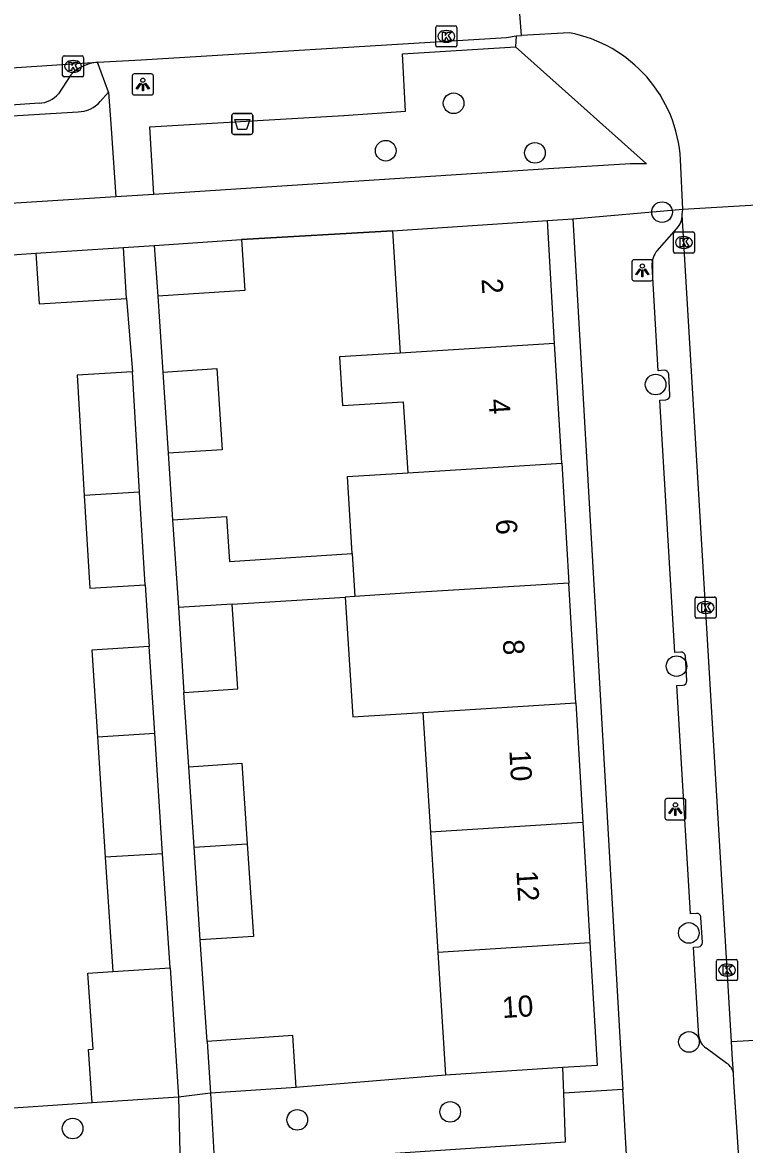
# Model space of a CAD drawing. Extents: x 159053 to 160041, y 380450 to 381422.
# Drawn here: x 159582.9 to 159617.1, y 381129.1 to 381182.3 of the extents above; entities that cross this region are included whole.
import ezdxf

# ---------------------------------------------------------------- set-up
doc = ezdxf.new("R2010")
doc.units = 0
for name, color, linetype in [('IMGEO_Afvalbak', 7, 'Continuous'), ('IMGEO_Boom', 7, 'Continuous'), ('IMGEO_Groenvoorziening', 7, 'Continuous'), ('IMGEO_Kolk', 7, 'Continuous'), ('IMGEO_Lichtpunt', 7, 'Continuous'), ('IMGEO_Muur', 7, 'Continuous'), ('IMGEO_Pand', 7, 'Continuous'), ('IMGEO_Pand_nummerreeks', 7, 'Continuous'), ('IMGEO_Rijbaan_lokaal_open', 7, 'Continuous'), ('IMGEO_Voetpad_open', 7, 'Continuous')]:
    doc.layers.add(name, color=color, linetype=linetype)

msp = doc.modelspace()

# ---------------------------------------------------------------- linework, layer by layer
at = {"layer": 'IMGEO_Afvalbak'}
for p, q in [((159592.854, 381177.078), (159592.854, 381177.878)), ((159592.854, 381177.878), (159592.854, 381177.078)), ((159592.954, 381177.978), (159593.744, 381177.978)), ((159593.744, 381177.978), (159592.954, 381177.978)), ((159593.844, 381177.878), (159593.844, 381177.078)), ((159593.844, 381177.078), (159593.844, 381177.878)), ((159593.744, 381176.978), (159592.954, 381176.978)), ((159592.954, 381176.978), (159593.744, 381176.978))]:
    msp.add_line(p, q, dxfattribs=at)
msp.add_lwpolyline([(159592.997, 381177.692), (159593.701, 381177.692), (159593.552, 381177.222), (159593.146, 381177.222), (159592.997, 381177.692)], dxfattribs=at)
for centre, start, end in [((159592.954, 381177.878), 90, 180), ((159592.954, 381177.878), 90, 180), ((159593.744, 381177.878), 0, 90), ((159593.744, 381177.878), 360, 90), ((159592.954, 381177.078), 180, 270), ((159592.954, 381177.078), 180, 270), ((159593.744, 381177.078), 270, 0), ((159593.744, 381177.078), 270, 0)]:
    msp.add_arc(centre, 0.1, start, end, dxfattribs=at)
at = {"layer": 'IMGEO_Boom'}
for centre in [(159603.362, 381178.456), (159600.148, 381176.211), (159607.215, 381176.108), (159613.236, 381173.3), (159612.932, 381165.134), (159613.922, 381151.794), (159614.502, 381139.152), (159614.511, 381133.992), (159603.2, 381130.677), (159595.954, 381130.298), (159585.316, 381129.889)]:
    msp.add_circle(centre, 0.489, dxfattribs=at)
at = {"layer": 'IMGEO_Groenvoorziening'}
for points in [[(159608.578, 381131.566), (159608.535, 381132.773)], [(159602.981, 381132.424), (159596.059, 381131.851), (159595.908, 381131.838)], [(159586.241, 381131.103), (159581.089, 381130.759)]]:
    msp.add_lwpolyline(points, dxfattribs=at)
at = {"layer": 'IMGEO_Kolk'}
for p, q in [((159602.516, 381181.199), (159602.516, 381182.051)), ((159602.591, 381182.125), (159603.443, 381182.125)), ((159603.517, 381182.051), (159603.517, 381181.199)), ((159603.004, 381181.905), (159603.029, 381181.905)), ((159603.443, 381181.125), (159602.591, 381181.125)), ((159603.027, 381181.345), (159603.002, 381181.345)), ((159584.836, 381179.778), (159584.836, 381180.63)), ((159584.911, 381180.704), (159585.763, 381180.704)), ((159585.324, 381180.484), (159585.349, 381180.484)), ((159585.837, 381180.63), (159585.837, 381179.778)), ((159585.347, 381179.924), (159585.322, 381179.924)), ((159585.763, 381179.704), (159584.911, 381179.704)), ((159613.77, 381171.438), (159613.77, 381172.29)), ((159613.845, 381172.364), (159614.697, 381172.364)), ((159614.258, 381172.144), (159614.283, 381172.144)), ((159614.771, 381172.29), (159614.771, 381171.438)), ((159614.281, 381171.584), (159614.256, 381171.584)), ((159614.697, 381171.364), (159613.845, 381171.364)), ((159614.796, 381154.142), (159614.796, 381154.994)), ((159614.871, 381155.068), (159615.723, 381155.068)), ((159615.797, 381154.994), (159615.797, 381154.142)), ((159615.284, 381154.848), (159615.309, 381154.848)), ((159615.723, 381154.068), (159614.871, 381154.068)), ((159615.307, 381154.288), (159615.282, 381154.288)), ((159615.889, 381137.897), (159616.741, 381137.897)), ((159615.814, 381136.971), (159615.814, 381137.823)), ((159616.302, 381137.677), (159616.327, 381137.677)), ((159616.815, 381137.823), (159616.815, 381136.971)), ((159616.741, 381136.897), (159615.889, 381136.897)), ((159616.325, 381137.117), (159616.3, 381137.117))]:
    msp.add_line(p, q, dxfattribs=at)
for points in [[(159602.516, 381181.199), (159602.516, 381182.051)], [(159602.591, 381182.125), (159603.443, 381182.125)], [(159603.517, 381182.051), (159603.517, 381181.199)], [(159602.837, 381181.825), (159602.96, 381181.825), (159602.96, 381181.674), (159603.09, 381181.825), (159603.254, 381181.825), (159603.108, 381181.674), (159603.261, 381181.425), (159603.109, 381181.425), (159603.024, 381181.589), (159602.96, 381181.522), (159602.96, 381181.425), (159602.837, 381181.425), (159602.837, 381181.825)], [(159603.443, 381181.125), (159602.591, 381181.125)], [(159584.836, 381179.778), (159584.836, 381180.63)], [(159584.911, 381180.704), (159585.763, 381180.704)], [(159585.837, 381180.63), (159585.837, 381179.778)], [(159585.157, 381180.404), (159585.28, 381180.404), (159585.28, 381180.253), (159585.41, 381180.404), (159585.574, 381180.404), (159585.428, 381180.253), (159585.581, 381180.004), (159585.429, 381180.004), (159585.344, 381180.168), (159585.28, 381180.101), (159585.28, 381180.004), (159585.157, 381180.004), (159585.157, 381180.404)], [(159585.763, 381179.704), (159584.911, 381179.704)], [(159613.77, 381171.438), (159613.77, 381172.29)], [(159613.845, 381172.364), (159614.697, 381172.364)], [(159614.091, 381172.064), (159614.214, 381172.064), (159614.214, 381171.913), (159614.344, 381172.064), (159614.508, 381172.064), (159614.362, 381171.913), (159614.515, 381171.664), (159614.363, 381171.664), (159614.278, 381171.828), (159614.214, 381171.761), (159614.214, 381171.664), (159614.091, 381171.664), (159614.091, 381172.064)], [(159614.771, 381172.29), (159614.771, 381171.438)], [(159614.697, 381171.364), (159613.845, 381171.364)], [(159614.796, 381154.142), (159614.796, 381154.994)], [(159614.871, 381155.068), (159615.723, 381155.068)], [(159615.797, 381154.994), (159615.797, 381154.142)], [(159615.117, 381154.768), (159615.24, 381154.768), (159615.24, 381154.617), (159615.37, 381154.768), (159615.534, 381154.768), (159615.388, 381154.617), (159615.541, 381154.368), (159615.389, 381154.368), (159615.304, 381154.532), (159615.24, 381154.465), (159615.24, 381154.368), (159615.117, 381154.368), (159615.117, 381154.768)], [(159615.723, 381154.068), (159614.871, 381154.068)], [(159615.889, 381137.897), (159616.741, 381137.897)], [(159615.814, 381136.971), (159615.814, 381137.823)], [(159616.135, 381137.597), (159616.258, 381137.597), (159616.258, 381137.446), (159616.388, 381137.597), (159616.552, 381137.597), (159616.406, 381137.446), (159616.559, 381137.197), (159616.407, 381137.197), (159616.322, 381137.361), (159616.258, 381137.294), (159616.258, 381137.197), (159616.135, 381137.197), (159616.135, 381137.597)], [(159616.815, 381137.823), (159616.815, 381136.971)], [(159616.741, 381136.897), (159615.889, 381136.897)]]:
    msp.add_lwpolyline(points, dxfattribs=at)
for centre, start, end in [((159602.593, 381182.049), 91.552, 178.448), ((159602.593, 381182.049), 91.552, 178.448), ((159603.441, 381182.049), 1.552, 88.448), ((159603.441, 381182.049), 1.552, 88.448), ((159602.593, 381181.201), 181.552, 268.448), ((159602.593, 381181.201), 181.552, 268.448), ((159603.441, 381181.201), 271.552, 358.448), ((159603.441, 381181.201), 271.552, 358.448), ((159584.913, 381180.628), 91.552, 178.448), ((159584.913, 381180.628), 91.552, 178.448), ((159585.761, 381180.628), 1.552, 88.448), ((159585.761, 381180.628), 1.552, 88.448), ((159584.913, 381179.78), 181.552, 268.448), ((159584.913, 381179.78), 181.552, 268.448), ((159585.761, 381179.78), 271.552, 358.448), ((159585.761, 381179.78), 271.552, 358.448), ((159613.847, 381172.288), 91.552, 178.448), ((159613.847, 381172.288), 91.552, 178.448), ((159614.695, 381172.288), 1.552, 88.448), ((159614.695, 381172.288), 1.552, 88.448), ((159613.847, 381171.44), 181.552, 268.448), ((159613.847, 381171.44), 181.552, 268.448), ((159614.695, 381171.44), 271.552, 358.448), ((159614.695, 381171.44), 271.552, 358.448), ((159614.873, 381154.992), 91.552, 178.448), ((159614.873, 381154.992), 91.552, 178.448), ((159615.721, 381154.992), 1.552, 88.448), ((159615.721, 381154.992), 1.552, 88.448), ((159614.873, 381154.144), 181.552, 268.448), ((159614.873, 381154.144), 181.552, 268.448), ((159615.721, 381154.144), 271.552, 358.448), ((159615.721, 381154.144), 271.552, 358.448), ((159615.891, 381137.821), 91.552, 178.448), ((159615.891, 381137.821), 91.552, 178.448), ((159616.739, 381137.821), 1.552, 88.448), ((159616.739, 381137.821), 1.552, 88.448), ((159615.891, 381136.973), 181.552, 268.448), ((159615.891, 381136.973), 181.552, 268.448), ((159616.739, 381136.973), 271.552, 358.448), ((159616.739, 381136.973), 271.552, 358.448)]:
    msp.add_arc(centre, 0.0765, start, end, dxfattribs=at)
for centre, major_axis, ratio, start_param, end_param in [((159603.003, 381181.625), (-0.387, 0.002), 0.722429, 4.712389, 7.853982), ((159603.028, 381181.625), (-0.39, 0.002), 0.717154, 1.570796, 4.712389), ((159585.323, 381180.204), (-0.387, 0.002), 0.722429, 4.712389, 7.853982), ((159585.348, 381180.204), (-0.39, 0.002), 0.717154, 1.570796, 4.712389), ((159614.257, 381171.864), (-0.387, 0.002), 0.722429, 4.712389, 7.853982), ((159614.282, 381171.864), (-0.39, 0.002), 0.717154, 1.570796, 4.712389), ((159615.283, 381154.568), (-0.387, 0.002), 0.722429, 4.712389, 7.853982), ((159615.308, 381154.568), (-0.39, 0.002), 0.717154, 1.570796, 4.712389), ((159616.301, 381137.397), (-0.387, 0.002), 0.722429, 4.712389, 7.853982), ((159616.326, 381137.397), (-0.39, 0.002), 0.717154, 1.570796, 4.712389)]:
    msp.add_ellipse(centre, major_axis=major_axis, ratio=ratio, start_param=start_param, end_param=end_param, dxfattribs=at)
at = {"layer": 'IMGEO_Lichtpunt'}
for p, q in [((159588.142, 381179.752), (159588.142, 381178.945)), ((159588.142, 381179.752), (159588.142, 381178.945)), ((159589.044, 381179.847), (159588.236, 381179.847)), ((159589.044, 381179.847), (159588.236, 381179.847)), ((159589.138, 381178.945), (159589.138, 381179.752)), ((159589.138, 381178.945), (159589.138, 381179.752)), ((159588.236, 381178.851), (159589.044, 381178.851)), ((159588.236, 381178.851), (159589.044, 381178.851)), ((159611.805, 381170.949), (159611.805, 381170.142)), ((159611.805, 381170.949), (159611.805, 381170.142)), ((159612.707, 381171.044), (159611.899, 381171.044)), ((159612.707, 381171.044), (159611.899, 381171.044)), ((159612.801, 381170.142), (159612.801, 381170.949)), ((159612.801, 381170.142), (159612.801, 381170.949)), ((159611.899, 381170.048), (159612.707, 381170.048)), ((159611.899, 381170.048), (159612.707, 381170.048)), ((159613.369, 381145.42), (159613.369, 381144.613)), ((159613.369, 381145.42), (159613.369, 381144.613)), ((159614.271, 381145.515), (159613.463, 381145.515)), ((159614.271, 381145.515), (159613.463, 381145.515)), ((159614.365, 381144.613), (159614.365, 381145.42)), ((159614.365, 381144.613), (159614.365, 381145.42)), ((159613.463, 381144.519), (159614.271, 381144.519)), ((159613.463, 381144.519), (159614.271, 381144.519))]:
    msp.add_line(p, q, dxfattribs=at)
for points in [[(159588.516, 381179.416), (159588.555, 381179.388), (159588.367, 381179.126), (159588.329, 381179.153), (159588.516, 381179.416)], [(159588.618, 381179.368), (159588.665, 381179.368), (159588.665, 381179.046), (159588.618, 381179.046), (159588.618, 381179.368)], [(159588.728, 381179.388), (159588.766, 381179.415), (159588.953, 381179.153), (159588.914, 381179.125), (159588.728, 381179.388)], [(159612.179, 381170.613), (159612.218, 381170.585), (159612.03, 381170.323), (159611.992, 381170.35), (159612.179, 381170.613)], [(159612.281, 381170.565), (159612.328, 381170.565), (159612.328, 381170.243), (159612.281, 381170.243), (159612.281, 381170.565)], [(159612.391, 381170.585), (159612.429, 381170.612), (159612.616, 381170.35), (159612.577, 381170.322), (159612.391, 381170.585)], [(159613.743, 381145.084), (159613.782, 381145.056), (159613.594, 381144.794), (159613.556, 381144.821), (159613.743, 381145.084)], [(159613.845, 381145.036), (159613.892, 381145.036), (159613.892, 381144.714), (159613.845, 381144.714), (159613.845, 381145.036)], [(159613.955, 381145.056), (159613.993, 381145.083), (159614.18, 381144.821), (159614.141, 381144.793), (159613.955, 381145.056)]]:
    msp.add_lwpolyline(points, dxfattribs=at)
for centre in [(159588.641, 381179.55), (159612.304, 381170.747), (159613.868, 381145.218)]:
    msp.add_circle(centre, 0.0994, dxfattribs=at)
for centre, start, end in [((159588.236, 381179.752), 90, 180), ((159588.236, 381179.752), 90, 180), ((159589.044, 381179.752), 0, 90), ((159589.044, 381179.752), 0, 90), ((159588.236, 381178.945), 180, 270), ((159588.236, 381178.945), 180, 270), ((159589.044, 381178.945), 270, 0), ((159589.044, 381178.945), 270, 360), ((159611.899, 381170.949), 90, 180), ((159611.899, 381170.949), 90, 180), ((159612.707, 381170.949), 0, 90), ((159612.707, 381170.949), 0, 90), ((159611.899, 381170.142), 180, 270), ((159611.899, 381170.142), 180, 270), ((159612.707, 381170.142), 270, 0), ((159612.707, 381170.142), 270, 360), ((159613.463, 381145.42), 90, 180), ((159613.463, 381145.42), 90, 180), ((159614.271, 381145.42), 0, 90), ((159614.271, 381145.42), 0, 90), ((159613.463, 381144.613), 180, 270), ((159613.463, 381144.613), 180, 270), ((159614.271, 381144.613), 270, 0), ((159614.271, 381144.613), 270, 360)]:
    msp.add_arc(centre, 0.0946, start, end, dxfattribs=at)
at = {"layer": 'IMGEO_Muur'}
for points in [[(159600.471, 381172.413), (159593.315, 381172.002)], [(159602.981, 381132.424), (159596.059, 381131.851)], [(159596.059, 381131.851), (159595.908, 381131.838)], [(159586.241, 381131.103), (159581.089, 381130.759)]]:
    msp.add_lwpolyline(points, dxfattribs=at)
at = {"layer": 'IMGEO_Pand'}
for points in [[(159600.471, 381172.413), (159607.804, 381172.906)], [(159608.147, 381167.082), (159607.804, 381172.906)], [(159589.184, 381171.723), (159593.315, 381172.002)], [(159593.315, 381172.002), (159593.478, 381169.591), (159589.347, 381169.312)], [(159600.471, 381172.413), (159600.834, 381166.624)], [(159583.572, 381171.364), (159587.717, 381171.624)], [(159587.869, 381169.213), (159587.717, 381171.624)], [(159589.184, 381171.723), (159589.347, 381169.312)], [(159583.572, 381171.364), (159583.724, 381168.953), (159587.869, 381169.213)], [(159600.834, 381166.624), (159597.96, 381166.444), (159598.104, 381164.14), (159600.979, 381164.32), (159601.191, 381160.949)], [(159608.147, 381167.082), (159600.834, 381166.624)], [(159608.482, 381161.405), (159608.147, 381167.082)], [(159588.146, 381165.739), (159585.523, 381165.581), (159585.865, 381159.871)], [(159588.488, 381160.036), (159588.146, 381165.739)], [(159589.585, 381165.72), (159592.14, 381165.888), (159592.395, 381162.036), (159589.839, 381161.876)], [(159589.585, 381165.72), (159589.839, 381161.876)], [(159601.191, 381160.949), (159608.482, 381161.405)], [(159608.482, 381161.405), (159608.817, 381155.73)], [(159598.562, 381157.132), (159598.334, 381160.77), (159601.191, 381160.949)], [(159588.488, 381160.036), (159585.865, 381159.871)], [(159585.865, 381159.871), (159586.129, 381155.483), (159588.751, 381155.64)], [(159588.751, 381155.64), (159588.488, 381160.036)], [(159590.048, 381158.716), (159592.603, 381158.876), (159592.744, 381156.748), (159598.562, 381157.132)], [(159590.048, 381158.716), (159590.322, 381154.572)], [(159598.562, 381157.132), (159598.689, 381155.096)], [(159608.817, 381155.73), (159601.547, 381155.275), (159598.689, 381155.096)], [(159609.152, 381150.054), (159608.817, 381155.73)], [(159592.877, 381154.732), (159598.226, 381155.067)], [(159598.689, 381155.096), (159598.226, 381155.067)], [(159598.226, 381155.067), (159598.582, 381149.392), (159601.903, 381149.6)], [(159592.877, 381154.732), (159590.322, 381154.572)], [(159590.322, 381154.572), (159590.588, 381150.549)], [(159590.588, 381150.549), (159593.142, 381150.718), (159592.877, 381154.732)], [(159588.941, 381152.719), (159586.225, 381152.543), (159586.492, 381148.447)], [(159589.208, 381148.618), (159588.941, 381152.719)], [(159601.903, 381149.6), (159609.152, 381150.054)], [(159601.903, 381149.6), (159602.259, 381143.925)], [(159609.152, 381150.054), (159609.487, 381144.378)], [(159586.492, 381148.447), (159589.208, 381148.618)], [(159589.579, 381142.909), (159589.208, 381148.618)], [(159586.492, 381148.447), (159586.863, 381142.737)], [(159590.821, 381147.028), (159593.337, 381147.194), (159593.59, 381143.381)], [(159591.072, 381143.224), (159590.821, 381147.028)], [(159609.487, 381144.378), (159602.259, 381143.925)], [(159609.487, 381144.378), (159609.821, 381138.701)], [(159602.259, 381143.925), (159602.615, 381138.25)], [(159591.072, 381143.224), (159593.59, 381143.381)], [(159591.363, 381138.822), (159591.072, 381143.224)], [(159593.59, 381143.381), (159593.881, 381138.989), (159591.363, 381138.822)], [(159589.579, 381142.909), (159586.863, 381142.737)], [(159586.863, 381142.737), (159587.215, 381137.324)], [(159589.931, 381137.5), (159589.579, 381142.909)], [(159602.615, 381138.25), (159609.821, 381138.701)], [(159609.821, 381138.701), (159610.165, 381132.875), (159608.535, 381132.773)], [(159602.615, 381138.25), (159602.981, 381132.424)], [(159587.215, 381137.324), (159589.931, 381137.5)], [(159589.931, 381137.5), (159590.335, 381131.38)], [(159586.241, 381131.103), (159586.07, 381133.636), (159586.282, 381133.65), (159586.039, 381137.248), (159587.215, 381137.324)], [(159595.908, 381131.838), (159595.742, 381134.291), (159591.681, 381134.016)], [(159591.681, 381134.016), (159591.847, 381131.564)], [(159608.535, 381132.773), (159602.981, 381132.424)], [(159595.908, 381131.838), (159591.847, 381131.564)], [(159590.335, 381131.38), (159586.241, 381131.103)]]:
    msp.add_lwpolyline(points, dxfattribs=at)
at = {"layer": 'IMGEO_Rijbaan_lokaal_open'}
for points in [[(159606.582, 381181.67), (159606.136, 381187.455)], [(159586.493, 381180.403), (159588.568, 381180.51), (159605.874, 381181.568), (159606.325, 381181.656)], [(159606.325, 381181.656), (159606.582, 381181.67)], [(159608.829, 381181.797), (159606.582, 381181.67)], [(159571.605, 381179.431), (159586.493, 381180.403)], [(159614.219, 381173.436), (159614.108, 381175.781)], [(159614.219, 381173.436), (159618.238, 381173.678)], [(159614.195, 381173.166), (159614.219, 381173.436)], [(159616.518, 381133.993), (159614.195, 381173.166)], [(159620.639, 381134.237), (159616.518, 381133.993)], [(159616.615, 381132.518), (159616.573, 381133.156), (159616.518, 381133.993)], [(159616.955, 381127.176), (159616.908, 381128.041), (159616.642, 381132.102), (159616.615, 381132.518)]]:
    msp.add_lwpolyline(points, dxfattribs=at)
msp.add_arc((159607.641, 381175.431), 6.476, 3.1005, 79.433, dxfattribs=at)
at = {"layer": 'IMGEO_Voetpad_open'}
for points in [[(159606.325, 381181.656), (159606.294, 381181.132)], [(159589.162, 381174.141), (159588.966, 381177.337), (159594.073, 381177.644), (159598.169, 381177.883), (159601.085, 381178.091), (159600.947, 381180.807), (159606.294, 381181.132)], [(159606.294, 381181.132), (159612.496, 381175.587), (159611.736, 381175.587), (159607.856, 381175.348), (159589.162, 381174.141)], [(159587.008, 381178.982), (159586.493, 381180.403)], [(159585.227, 381179.81), (159584.647, 381178.903)], [(159586.62, 381178.547), (159587.008, 381178.982)], [(159587.008, 381178.982), (159587.146, 381177.256), (159587.36, 381174.029)], [(159583.732, 381178.458), (159574.526, 381177.82)], [(159574.594, 381177.386), (159585.57, 381178.059)], [(159587.36, 381174.029), (159567.657, 381172.785)], [(159589.162, 381174.141), (159587.36, 381174.029)], [(159607.804, 381172.906), (159609.008, 381172.981)], [(159609.008, 381172.981), (159614.219, 381173.436)], [(159609.008, 381172.981), (159611.37, 381131.744)], [(159613.007, 381171.474), (159613.941, 381172.532)], [(159593.315, 381172.002), (159600.471, 381172.413)], [(159587.717, 381171.624), (159589.184, 381171.723)], [(159579.051, 381171.042), (159583.572, 381171.364)], [(159613.339, 381165.807), (159613.053, 381165.79), (159612.759, 381170.753)], [(159589.347, 381169.312), (159589.585, 381165.72)], [(159587.869, 381169.213), (159588.146, 381165.739)], [(159613.609, 381164.624), (159613.55, 381165.619)], [(159614.13, 381152.458), (159613.845, 381152.441), (159613.136, 381164.396), (159613.421, 381164.413)], [(159589.839, 381161.876), (159590.048, 381158.716)], [(159588.751, 381155.64), (159588.941, 381152.719)], [(159614.411, 381151.098), (159614.342, 381152.27)], [(159614.864, 381140.081), (159614.579, 381140.064), (159613.938, 381150.87), (159614.223, 381150.887)], [(159590.821, 381147.028), (159590.588, 381150.549)], [(159615.146, 381138.707), (159615.075, 381139.893)], [(159591.681, 381134.016), (159591.363, 381138.822)], [(159614.985, 381134.251), (159614.724, 381138.482), (159614.958, 381138.496)], [(159616.306, 381132.976), (159615.319, 381133.7)], [(159591.847, 381131.564), (159590.335, 381131.38)], [(159591.847, 381131.564), (159592.04, 381128.159), (159596.333, 381128.442), (159608.66, 381129.256), (159608.578, 381131.566)], [(159611.37, 381131.744), (159608.578, 381131.566)], [(159611.644, 381126.931), (159611.37, 381131.744)], [(159590.335, 381131.38), (159590.41, 381128.083), (159578.93, 381127.348)]]:
    msp.add_lwpolyline(points, dxfattribs=at)
for centre, radius, start, end in [((159586.716, 381178.279), 2.135, 95.9901, 134.2071), ((159583.643, 381179.805), 1.35, 273.8003, 318.0706), ((159585.584, 381179.403), 1.344, 269.4091, 320.4454), ((159613.167, 381173.21), 1.029, 318.7883, 357.5466), ((159613.762, 381170.811), 1.005, 138.7277, 183.3093), ((159613.35, 381165.607), 0.2, 3.3442, 93.2541), ((159613.409, 381164.613), 0.2, 273.3442, 3.2541), ((159614.142, 381152.258), 0.2, 3.3561, 93.5111), ((159614.211, 381151.087), 0.2, 273.3442, 3.2541), ((159614.877, 381139.883), 0.198, 2.8847, 93.7135), ((159614.946, 381138.696), 0.2, 273.3442, 3.2541), ((159615.749, 381134.338), 0.769, 186.4595, 235.9865), ((159615.911, 381132.376), 0.719, 11.3995, 56.6134)]:
    msp.add_arc(centre, radius, start, end, dxfattribs=at)

# ---------------------------------------------------------------- texts
at = {"layer": 'IMGEO_Pand_nummerreeks'}
for s, rotation, p in [('2', 273.3754, (159604.682, 381170.139)), ('4', 273.3745, (159605.017, 381164.436)), ('6', 273.3745, (159605.354, 381158.735)), ('8', 273.3745, (159605.69, 381153.031)), ('10', 273.3754, (159606, 381147.791)), ('12', 273.3754, (159606.336, 381142.096)), ('10', 3.5922, (159605.684, 381135.119))]:
    msp.add_text(s, height=1, rotation=rotation, dxfattribs=at).set_placement(p)

doc.saveas('drawing.dxf')
